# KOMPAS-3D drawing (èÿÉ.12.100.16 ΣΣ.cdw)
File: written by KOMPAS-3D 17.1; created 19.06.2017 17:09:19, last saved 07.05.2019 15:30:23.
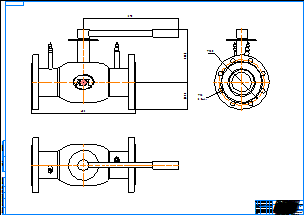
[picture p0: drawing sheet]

Sheet 1: A0, landscape

Title block, sheet 1: name: КШР.12.100.16 фф; material: Внимание! Данный продукт является объектом авторского права ООО «Торговый Дом АДЛ». / Запрещается изменение, копирование, распространение / (в том числе путем копирования на другие сайты и ресурсы в Интернете) / или любое иное использование информации и объектов без предварительного / согласия правообладателя (ООО «Торговый Дом АДЛ»).; scale: 1:1; sheets: 1; organisation: ООО "Торговый дом АДЛ"; sheet format: A0; stored path: C:\Users\tra\Desktop\2д чертежи\Шаровые краны БИВАЛ\КШР_Бивал_серия_12\KOMPAS 2D\КШР.12.100.16 фф.cdw

Views: Спереди 1, Проекционный вид 2, Проекционный вид 3
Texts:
  Klimkovich
  ADL
Dimensions and other numbers on the sheet: 405; 370; 205,1; 107,5; 180; 18; 8 Отв.; 1:1; 1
